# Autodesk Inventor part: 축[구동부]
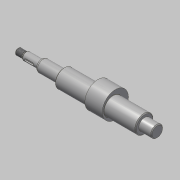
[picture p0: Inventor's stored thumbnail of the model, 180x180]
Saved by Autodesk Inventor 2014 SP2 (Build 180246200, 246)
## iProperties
Created: 2015-12
Part Number: 축[구동부]
Document SubType Name: Modeling
Designer: mdu
Density: 7.86 g/cm^3
Material: 강철, 연강
Appearance: 강철
Mass: 484.681 g
Surface Area: 125.968 cm^2
Volume: 61.6642 cm^3
Author: mdu
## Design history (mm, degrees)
sketch "스케치1"
  geometry: L1 (62, 100.9)-(62, 67.1) reference; L2 (51, 101.2)-(51, 84) reference; L3 (-51, 84)-(-51, 101.2) reference; L4 (-62, 67.1)-(-62, 100.9) reference; L5 (-51.6, 91.5)-(-61.4, 91.5) reference; L6 (51.6, 91.5)-(61.4, 91.5) reference; L7 (67, 84)-(-109, 84); L8 (-77, 64.201)-(-77, 103.799) reference; L9 (67, 84)-(67, 91.5); L10 (67, 91.5)-(51, 91.5); L11 (51, 91.5)-(51, 95.5); L12 (51, 95.5)-(-51, 95.5); L13 (-51, 95.5)-(-51, 91.5); L14 (-51, 91.5)-(-79, 91.5); L15 (-79, 91.5)-(-79, 89); L16 (-79, 89)-(-99, 89); L17 (-99, 89)-(-99, 87); L18 (-100.5, 88)-(-109, 88); L19 (-109, 88)-(-109, 84); L20 (-99, 87)-(-100.5, 87); L21 (-100.5, 87)-(-100.5, 88); 2 further points
  constraints: 32 end point, 7 parallel, 6 point on line, 5 perpendicular, 2 collinear, 2 horizontal, 1 midpoint, 4 other
  dimensions: "d0" = 5 distance from line of L7.start L1; "d2" = 2 distance between parallel lines of L15 L8; "d3" = 23 diameter of L12 L7; "d4" = 10 diameter of L16 L7; "d5" = 1.5 distance of L17.end L20.end; "d6" = 6 diameter of L20 L7; "d7" = 20 distance of L15.end L16.end; "d8" = 10 distance between parallel lines of L17 L19; "d9" = 8 diameter of L18 L7
revolve "회전1" sketch "스케치1" stored, may be unused: angle "d10" = 90 deg
sketch "스케치2"
  geometry: C1 r 11.5 at (84, 0) reference; C2 r 11.5 at (84, 0) reference; C3 r 16.5 at (87, 0); 1 further point
  constraints: 1 centre point, 1 horizontal alignment
  dimensions: "d11" = 33 diameter of C3; "d12" = 3 distance of C3.centre C1.centre
extrude "돌출1" join sketch "스케치2" stored distance "d13" = 22; taper "d14" = 0 deg
chamfer "모따기1" distance "d15" = 1; stored, may be unused: second distance "d16" = 2, angle "d17" = 45 deg
feature "스레드1" dims "d18" = 10, "d19" = 0
node "작업 평면1"
sketch "스케치3"
  geometry: L1 (-5.5, -1.5)-(3.5, -1.5); L2 (3.5, 1.5)-(-5.5, 1.5); L3 (-10, -4)-(-10, 4) reference; A1 r 1.5 centre (3.5, 0) between (3.5, -1.5) and (3.5, 1.5); A2 r 1.5 centre (-5.5, 0) between (-5.5, 1.5) and (-5.5, -1.5); 2 further points
  constraints: 4 end point, 4 point on circle, 4 tangent, 2 centre point, 1 horizontal, 1 horizontal alignment, 1 midpoint, 1 parallel
  dimensions: "d20" = 3 distance between parallel lines of L1 L2; "d21" = 12 dimension on A1 A2; "d22" = 3 distance edge to line of A2 L3
extrude "돌출2" cut sketch "스케치3" distance "d23" = 1.8; taper "d24" = 0 deg
fillet "모깎기1" dims "d25" = 0.3
fillet "모깎기2" dims "d26" = 3
node "솔리드1"
node "참조1"
node "참조2"
node "참조3"
node "참조4"
node "참조5"
node "투영된 루프1"
